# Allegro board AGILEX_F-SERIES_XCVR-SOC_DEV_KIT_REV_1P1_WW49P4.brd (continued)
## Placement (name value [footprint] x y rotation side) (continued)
R424  1K  [0402]  84.96 40.26 180 bottom
R425  1K  [0402]  83.57 40.26 180 bottom
R426  0  [0402]  94.21 33.53 270 bottom
R427  0  [0402]  94.21 34.54 270 bottom
R428  1K  [0402]  102.97 37.72 270 bottom
R429  0  [0402]  159.9 136.01 90 top
R430  0  [0402]  159.9 135 90 top
R431  0  [0402]  162.41 130.94 180 top
R432  0  [0402]  163.42 130.94 180 top
R433  1K  [0402]  170.15 142.05 0 top
R434  1K  [0402]  170.15 139.89 0 top
R435  DNI  [0402]  168.88 142.05 180 top
R436  1K  [0402]  161.01 130.81 0 top
R437  4.7K  [0402]  155.07 35.89 180 bottom
R438  10.0K  [0402]  154.81 101.85 90 top
R439  0  [0402]  159.99 34.29 90 bottom
R440  0  [0402]  159.99 33.02 90 bottom
R441  0  [0402]  161.29 94.36 270 top
R442  0  [0402]  159.99 29.21 90 bottom
R443  0  [0402]  159.99 27.94 90 bottom
R444  22  [0402]  155.57 27.51 180 bottom
R445  4.7K  [0402]  46.99 111.89 270 bottom
R446  10.0K  [0402]  52.58 168.78 270 top
R447  0  [0402]  46.1 162.31 90 top
R448  4.7K  [0402]  50.42 112.9 180 bottom
R449  0  [0402]  54.96 111.25 90 bottom
R450  0  [0402]  55.19 107.57 90 bottom
R451  0  [0402]  55.19 106.3 90 bottom
R452  0  [0402]  50.93 105.41 0 bottom
R453  4.7K  [0402]  186.28 49.4 0 top
R454  DNI  [0402]  187.42 47.37 0 top
R455  3.3K  [0402]  191.01 60.13 90 top
R456  DNI  [0402]  180.09 62.48 90 top
R457  DNI  [0402]  186.82 62.48 90 top
R458  0  [0402]  190.98 56.01 270 top
R459  0  [0402]  190.98 57.02 270 top
R460  100  [0402]  182.63 62.48 90 top
R461  0  [0402]  176.76 52.7 90 top
R462  0  [0402]  176.78 51.56 90 top
R463  22  [0402]  190.9 35.43 90 top
R464  124  [0402]  187.96 62.23 270 bottom
R465  0  [0402]  191.13 51.82 270 top
R466  0  [0402]  191.13 52.83 270 top
R467  DNI  [0402]  190.9 34.21 270 top
R468  374  [0402]  187.96 63.63 90 bottom
R469  124  [0402]  184.78 48.01 90 top
R470  DNI  [0402]  181.46 48.77 180 top
R471  DNI  [0402]  182.98 48.77 180 top
R472  374  [0402]  184.76 49.15 270 top
R475  0  [0402]  191.01 59.09 90 top
R476  1.00K  [0402]  179.8 42.29 0 top
R478  49.9  [0402]  172.06 58.8 90 top
R479  DNI  [0402]  164.44 47.12 270 top
R480  DNI  [0402]  145.77 91.44 270 bottom
R481  DNI  [0402]  145.77 92.71 270 bottom
R482  DNI  [0402]  143.48 92.71 90 bottom
R483  2.0K  [0402]  181.33 123.32 270 top
R484  10.0K  [0402]  181.74 128.52 180 top
R485  2.0K  [0402]  179.3 123.32 90 top
R486  10.0K  [0402]  180.47 128.52 180 top
R487  0  [0402]  143.48 91.44 90 bottom
R488  0  [0402]  143.48 95.25 90 bottom
R490  0  [0402]  180.09 95 270 top
R491  0  [0402]  180.09 93.73 270 top
R493  DNI  [0402]  180.09 92.46 270 top
R494  DNI  [0402]  180.09 96.27 270 top
R495  10.0K  [0402]  145.03 163.96 180 top
R496  10.0K  [0402]  146.18 152.4 90 bottom
R497  DNI  [0402]  172.72 121.28 180 top
R498  DNI  [0402]  171.32 121.28 180 top
R499  DNI  [0402]  183.64 125.73 0 top
R500  10.0K  [0402]  171.04 123.32 270 top
R501  10.0K  [0402]  173.07 123.32 90 top
R502  DNI  [0402]  61.47 44.7 270 bottom
R504  DNI  [0402]  175.51 125.73 0 top
R505  0  [0402]  61.47 45.97 90 bottom
R506  10.0K  [0402]  173.35 128.27 180 top
R507  10.0K  [0402]  172.34 128.27 180 top
R508  4.7K  [0402]  146.71 34.36 90 bottom
R509  40.2K  [0402]  36.34 193.42 270 bottom
R511  DNI  [0402]  36.42 186.44 0 top
R512  10.0K  [0402]  36.34 192.28 270 bottom
R513  10  [0402]  35.91 193.67 0 top
R514  0  [0402]  31.85 193.67 180 top
R515  20.0K  [0402]  30.71 193.67 0 top
R516  DNI  [0402]  35.15 186.44 0 top
R517  DNI  [0402]  52.32 212.85 0 bottom
R518  1.00K  [0402]  34.39 193.17 270 top
R519  DNI  [0402]  37.69 186.44 0 top
R520  3.3K  [0402]  7.97 186.56 90 bottom
R521  DNI  [0402]  31.72 186.69 90 bottom
R522  DNI  [0402]  11.53 182.4 0 top
R523  DNI  [0402]  13.33 140.49 0 top
R524  DNI  [0402]  33.37 187.2 180 bottom
R528  10.0K  [0402]  45.47 56.64 90 bottom
R529  422.00  [0402]  8.1 183.9 270 bottom
R530  10.0K  [0402]  45.47 55.75 270 bottom
R533  6.34M  [0402]  57.53 189.99 270 top
R534  10  [0402]  57.63 203.2 270 top
R535  1.00K  [0402]  50.26 191.26 90 top
R536  1K  [0402]  50.26 186.18 270 top
R537  DNI  [0402]  50.26 184.78 270 top
R538  DNI  [0402]  50.26 187.58 90 top
R539  45.3K  [0402]  55.88 189.36 180 top
R540  255K  [0402]  57.53 188.72 90 top
R541  3.3K  [0402]  190.98 214.18 180 bottom
R542  10.0K  [0402]  50.26 189.36 270 top
R543  1K  [0402]  181.91 196.06 0 top
R544  DNI  [0402]  180.67 196.06 0 top
R546  10.0K  [0402]  191.26 133.73 0 top
R547  DNI  [0402]  179.44 196.06 180 top
R548  10.0K  [0402]  189.99 133.73 180 top
R553  787  [0402]  205.36 185.17 0 top
R554  DNI  [0402]  34.11 148.74 270 bottom
R555  0  [0402]  32 148.74 90 bottom
R558  0  [0402]  43.99 25.53 180 top
R559  0  [0402]  42.85 25.53 180 top
R563  DNI  [0402]  207.49 184.89 180 bottom
R564  DNI  [0402]  201.78 184.73 180 bottom
R565  1K  [0402]  201.75 187.15 180 bottom
R566  DNI  [0402]  200.51 184.73 180 bottom
R569  0  [0402]  206.22 184.89 0 bottom
R573  422.00  [0402]  187.58 214.12 0 bottom
R574  DNI  [0402]  81.15 212.3 270 bottom
R575  DNI  [0402]  81.13 211.04 270 bottom
R576  DNI  [0402]  82.19 209.6 270 bottom
R636  10.0K  [0402]  37.28 162.1 180 bottom
R639  DNI  [0402]  30.33 146.81 180 bottom
R640  0  [0402]  31.34 146.81 180 bottom
R641  1K  [0402]  200.36 121.64 180 bottom
R643  0  [0402]  122.43 111.96 270 bottom
R644  0  [0402]  122.43 111.07 270 bottom
R646  DNI  [0402]  206.1 119.33 180 bottom
R647  DNI  [0402]  198.98 119.35 180 bottom
R648  DNI  [0402]  200.28 119.33 180 bottom
R654  0  [0402]  204.83 119.35 0 bottom
R658  10.0K  [0402]  36.17 160.02 180 top
R661  DNI  [0402]  32.48 146.81 180 bottom
R662  0  [0402]  33.5 146.81 0 bottom
R663  1K  [0402]  195.07 173.86 90 bottom
R666  0  [0402]  109.83 120.01 180 bottom
R667  0  [0402]  111.1 120.01 180 bottom
R668  6.34k  [0402]  215.39 167.39 180 bottom
R670  0  [0402]  184.35 168.12 270 bottom
R671  DNI  [0402]  187.32 165.48 90 bottom
R672  DNI  [0402]  187.32 168.28 90 bottom
R673  DNI  [0402]  187.32 166.88 90 bottom
R676  0  [0402]  189.1 165.1 180 bottom
R680  0  [0402]  24.31 43.48 0 bottom
R681  0.001  [WSL2010]  18.59 40.64 90 bottom
R682  DNI  [0402]  22.1 43.64 0 bottom
R684  19.6K  [0402]  26.9 42.6 180 bottom
R686  1K  [0402]  25.63 42.6 180 bottom
R687  Î  [0402]  29.39 41.91 180 top
R690  0.004  [0805]  130.53 26.83 180 bottom
R693  0  [0402]  140.11 21.74 0 bottom
R694  1K  [0402]  140.49 20.09 90 bottom
R695  DNI  [0402]  141.38 21.74 0 bottom
R697  10.0K  [0402]  50.52 167.89 270 bottom
R701  0  [0402]  7.72 44.88 90 bottom
R702  1K  [0402]  9.37 45.26 180 bottom
R703  0.001  [WSL2010]  2.67 45.26 90 bottom
R704  DNI  [0402]  7.72 46.15 90 bottom
R707  10.0K  [0402]  11.99 44.78 90 top
R718  0.004  [0805]  35.94 41.12 180 bottom
R719  DNI  [0402]  34.95 44.98 90 bottom
R722  0  [0402]  34.95 45.95 90 bottom
R724  1K  [0402]  36.83 44.09 180 bottom
R725  10.0K  [0402]  46.56 43.41 90 top
R728  0.04  [0805]  57.48 130.76 270 top
R731  DNI  [0402]  55.07 144.53 270 top
R732  0  [0402]  55.09 145.85 270 top
R734  1K  [0402]  57.38 145.92 270 top
R736  0.1  [0805]  50.37 50.88 180 top
R739  DNI  [0402]  66.93 53.11 90 top
R740  0  [0402]  66.93 51.84 90 top
R742  1K  [0402]  64.64 51.84 90 top
R744  DNI  [0402]  74.04 48.9 90 top
R745  10.0K  [0402]  74.04 47.62 90 top
R746  0  [0402]  74.04 50.16 270 top
R747  1K  [0402]  74.04 51.44 90 top
R750  0.001  [WSL2010]  112.99 28.22 0 bottom
R751  DNI  [0402]  116.64 21.74 0 bottom
R754  0  [0402]  115.37 21.74 0 bottom
R756  1K  [0402]  115.75 20.09 90 bottom
R757  10.0K  [0402]  46.94 167.59 0 bottom
R759  60.4k  [0402]  118.62 17.45 180 bottom
R760  37.4k  [0402]  118.75 19.53 90 bottom
R762  4.7K  [0402]  118.49 13.06 270 bottom
R763  4.7K  [0402]  119.38 23.85 90 bottom
R764  10.0K  [0402]  145.29 140.21 180 top
R765  DNI  [0402]  142.93 140.36 270 top
R766  0  [0402]  142.48 139.92 180 bottom
R767  1K  [0402]  140.84 140.34 90 top
R770  0  [0402]  161.93 25.43 0 bottom
R771  DNI  [0402]  163.19 25.43 0 bottom
R775  1K  [0402]  163.19 21.92 180 bottom
R776  10.0K  [0402]  47.14 164.51 0 bottom
R779  0  [0402]  95.22 21.74 0 bottom
R780  DNI  [0402]  96.49 21.74 0 bottom
R784  1K  [0402]  95.61 20.09 90 bottom
R785  10.0K  [0402]  50.52 168.91 270 bottom
R791  0  [0402]  46.18 18.97 90 top
R792  10.0K  [0402]  47.75 17.98 180 bottom
R794  60.4k  [0402]  40.46 16.43 0 bottom
R839  1.00K  [0402]  80.36 63.5 0 bottom
R841  1.00K  [0402]  65.99 80.82 90 bottom
R842  1.00K  [0402]  67.89 88.39 180 bottom
R843  1.00K  [0402]  35.31 17.65 0 top
R844  DNI  [0402]  30.1 135.13 180 bottom
R845  DNI  [0402]  102.97 36.45 90 bottom
R846  1K  [0402]  93.44 37.34 180 bottom
R847  1K  [0402]  168.88 139.89 180 top
R848  DNI  [0402]  167.49 130.94 0 top
R849  DNI  [0402]  46.99 110.87 270 bottom
R850  1K  [0402]  187.42 49.4 180 top
R851  1K  [0402]  182.37 125.73 0 top
R852  1K  [0402]  174.12 125.73 0 top
R855  0  [0402]  158.92 80.4 0 top
R856  0  [0402]  157.52 80.4 0 top
R857  4.70K  [0402]  154.28 151.76 180 bottom
R858  1.00K  [0402]  96.6 108.6 180 bottom
R859  1.00K  [0402]  96.27 106.78 300 bottom
R860  1.00K  [0402]  98.02 104.9 300 bottom
R861  1.00K  [0402]  97.89 105.79 300 bottom
R862  1.00K  [0402]  98.34 108.6 180 bottom
R863  1.00K  [0402]  98.77 106.85 60 bottom
R864  1.00K  [0402]  97.47 109.1 180 bottom
R865  1.00K  [0402]  97.51 107.11 0 bottom
R866  1.00K  [0402]  99.64 108.35 60 bottom
R867  1.00K  [0402]  99.64 107.35 60 bottom
R870  DNI  [0402]  155.29 206.76 270 bottom
R871  DNI  [0402]  155.29 205.49 270 bottom
R872  4.7K  [0402]  176.76 57.4 270 top
R873  4.7K  [0402]  191.01 58.04 270 bottom
R874  4.7K  [0402]  181.76 63.24 0 bottom
R875  4.7K  [0402]  180.24 63.24 0 bottom
R878  DNI  [0402]  164.47 50.67 270 top
R879  DNI  [0402]  164.47 51.69 270 top
R880  4.7K  [0402]  180.97 72.52 180 top
R881  4.7K  [0402]  181.99 72.52 180 top
R883  4.7K  [0402]  179.42 50.29 90 bottom
R884  4.7K  [0402]  179.42 51.56 90 bottom
R885  10.0K  [0402]  189.33 54.99 90 bottom
R886  10.0K  [0402]  189.33 56.13 90 bottom
R887  4.7K  [0402]  176.76 58.93 270 top
R888  4.7K  [0402]  176.76 60.07 270 top
R889  4.7K  [0402]  176.76 55.63 270 top
R890  4.7K  [0402]  176.76 54.61 270 top
R891  4.7K  [0402]  183.02 72.5 180 top
R892  4.7K  [0402]  184.02 72.52 180 top
R893  4.7K  [0402]  164.47 43.94 270 top
R894  4.7K  [0402]  164.47 44.96 270 top
R895  4.7K  [0402]  164.47 53.21 270 top
R896  4.7K  [0402]  164.47 54.23 270 top
R897  4.7K  [0402]  164.47 55.24 270 top
R898  4.7K  [0402]  164.47 56.26 270 top
R899  DNI  [0402]  80.26 34.16 90 top
R900  DNI  [0402]  80.26 35.18 90 top
R901  DNI  [0402]  161.9 34.29 270 top
R902  DNI  [0402]  161.9 33.02 270 top
R903  DNI  [0402]  161.9 29.21 270 top
R904  DNI  [0402]  161.9 27.94 270 top
R905  DNI  [0402]  57.28 110.06 270 top
R906  DNI  [0402]  57.28 111.33 270 top
R907  DNI  [0402]  193.11 56.01 90 bottom
R908  DNI  [0402]  193.14 57.02 90 bottom
R909  DNI  [0402]  174.34 61.47 270 top
R910  10.0K  [0402]  191.01 61.16 90 top
R911  DNI  [0402]  181.46 46.86 0 top
R912  DNI  [0402]  182.98 46.86 0 top
R913  4.7K  [0402]  164.47 48.64 270 top
R914  4.7K  [0402]  164.47 49.66 270 top
R915  22  [0402]  184.78 46.74 90 top
R916  DNI  [0402]  168.37 74.42 270 top
R917  100  [0402]  172.06 61.47 90 top
R918  DNI  [0402]  102.97 35.31 270 bottom
R919  DNI  [0402]  166.22 74.42 270 top
R920  DNI  [0402]  180.19 40.64 90 top
R921  DNI  [0402]  140.94 80.01 90 bottom
R922  0  [0402]  33.75 155.7 270 bottom
R923  10.0K  [0402]  166.72 128.52 180 top
R924  10.0K  [0402]  165.45 128.52 180 top
R925  0  [0402]  172.44 132.97 90 top
R926  0  [0402]  172.44 131.7 90 top
R927  0  [0402]  161.29 92.2 270 top
R928  10.0K  [0402]  29.33 165.86 0 bottom
R929  10.0K  [0402]  212.6 20.83 90 bottom
R930  10.0K  [0402]  212.6 19.56 90 bottom
R931  1.00K  [0402]  167.39 104.01 180 top
R932  0  [0402]  84.05 150.62 90 bottom
R933  0  [0402]  95.98 151 0 bottom
R934  0  [0402]  107.41 151 0 bottom
R935  0  [0402]  118.84 151.18 0 bottom
R936  0  [0402]  73.12 151 0 bottom
R937  240  [0402]  120.02 117.09 0 bottom
R938  240  [0402]  132.08 117.09 0 bottom
R939  422.00  [0402]  186.54 148.59 180 bottom
R940  0  [0402]  136.14 76.96 0 bottom
R941  0  [0402]  177.67 22.16 180 top
R942  0  [0402]  176.4 22.16 180 top
R943  DNI  [0402]  177.67 21.27 0 top
R944  DNI  [0402]  176.4 21.27 0 top
R945  10.0K  [0402]  187.81 153.86 0 bottom
R946  10.0K  [0402]  192.38 153.86 0 bottom
R947  0  [0402]  114.81 121.94 180 bottom
R948  DNI  [0402]  116.43 121.28 180 bottom
R949  120  [0402]  116.48 119.18 180 bottom
R950  DNI  [0402]  67.31 94.74 270 bottom
R951  DNI  [0402]  67.31 96.01 270 bottom
R952  DNI  [WSL2010]  66.34 116.48 270 top
R953  33  [0402]  143.48 88.9 90 bottom
R954  33  [0402]  143.48 90.17 90 bottom
R955  33  [0402]  143.48 93.98 90 bottom
R956  33  [0402]  140.94 91.44 90 bottom
R957  33  [0402]  140.94 86.36 90 bottom
R958  33  [0402]  140.94 87.63 90 bottom
R959  33  [0402]  140.94 92.71 90 bottom
R960  33  [0402]  140.94 95.25 90 bottom
R961  33  [0402]  140.94 81.28 270 bottom
R962  33  [0402]  140.94 90.17 270 bottom
R963  33  [0402]  140.94 88.9 270 bottom
R964  33  [0402]  140.94 93.98 270 bottom
R965  33  [0402]  140.94 85.09 270 bottom
R966  33  [0402]  140.94 83.82 270 bottom
R967  33  [0402]  140.94 82.55 270 bottom
R968  0  [0402]  165.45 130.94 180 top
R969  0  [0402]  166.47 130.94 180 top
R970  DNI  [0402]  157.74 137.08 270 top
R971  1K  [0402]  159.9 137.08 270 top
R972  1K  [0402]  163.8 142.05 180 top
R973  DNI  [0402]  163.8 139.89 180 top
R974  1K  [0402]  172.46 134.07 90 top
R975  DNI  [0402]  170.41 134.11 90 top
R976  0  [0402]  26.77 22.22 0 top
R977  0  [0402]  18.26 172.85 180 top
R980  1M  [1206]  9.42 25.48 0 bottom
R981  0  [0402]  171.85 98.96 270 bottom
R982  4.7K  [0402]  55.58 52.53 180 bottom
R984  10.0K  [0402]  43.51 56.64 90 bottom
R985  10.0K  [0402]  43.51 55.73 90 bottom
R986  499  [0402]  149.32 208.48 90 bottom
R987  10.0K  [0402]  154.28 203.45 90 bottom
R988  10.0K  [0402]  155.8 203.96 180 bottom
R989  10.0K  [0402]  154.28 204.47 270 bottom
R990  10.0K  [0402]  29.8 163.93 180 bottom
R991  10.0K  [0402]  28.93 161.8 0 top
R992  10.0K  [0402]  166.25 199.03 270 bottom
R993  10.0K  [0402]  166.25 200.65 270 bottom
R994  10.0K  [0402]  166.25 202.26 270 bottom
R995  10.0K  [0402]  166.25 203.88 270 bottom
R996  10.0K  [0402]  161.29 90.93 90 top
R997  0.001  [WIDE2512]  29.44 199.01 90 top
R998  0.001  [WIDE2512]  29.44 206.63 90 top
R999  4.7K  [0402]  164.47 45.97 270 top
R1000  DNI  [0402]  31.98 17.53 90 top
R1001  10.0K  [0402]  212.57 28.57 270 top
R1003  1K  [0402]  95.61 37.34 180 bottom
R1004  DNI  [0402]  156.25 80.4 180 top
R1005  DNI  [0402]  31.62 179.32 180 bottom
R1006  DNI  [0402]  87.2 153.31 90 bottom
R1007  DNI  [0402]  98.68 153.29 90 bottom
R1008  DNI  [0402]  110.06 153.31 90 bottom
R1009  DNI  [0402]  121.51 153.31 90 bottom
R1010  DNI  [0402]  75.77 153.31 90 bottom
R1013  DNI  [0402]  26.64 122.25 270 bottom
R1014  0  [0402]  26.64 123.52 270 bottom
R1018  1K  [0402]  24.99 123.14 0 bottom
R1019  10.0K  [0402]  21.98 123.7 270 bottom
R1024  0.004  [0805]  33.51 139.09 0 top
R1025  0  [0402]  135.38 80.01 0 bottom
R1026  0  [0402]  114.81 120.04 180 bottom
R1027  0  [0402]  114.78 114.43 180 bottom
R1028  0  [0402]  127.23 113.92 270 bottom
R1029  36  [0402]  129.13 145.54 90 top
R1030  36  [0402]  129.13 148.34 90 top
R1031  36  [0402]  129.13 153.67 270 bottom
R1032  36  [0402]  123.42 157.48 180 top
R1033  36  [0402]  129.13 153.67 90 top
R1034  36  [0402]  129.13 151.89 270 bottom
R1035  36  [0402]  129.13 152.78 90 top
R1036  36  [0402]  129.13 147.45 270 bottom
R1037  36  [0402]  126.08 157.48 180 top
R1038  36  [0402]  121.64 157.48 180 top
R1039  36  [0402]  125.19 157.48 180 top
R1040  36  [0402]  122.53 157.48 180 top
R1041  36  [0402]  129.13 149.22 270 bottom
R1042  36  [0402]  129.13 151 270 bottom
R1043  36  [0402]  129.13 149.22 90 top
R1044  36  [0402]  129.13 146.43 90 top
R1045  36  [0402]  129.13 147.45 90 top
R1046  36  [0402]  129.13 148.34 270 bottom
R1047  36  [0402]  129.13 152.78 270 bottom
R1048  36  [0402]  119.86 157.48 180 top
R1049  36  [0402]  124.31 157.48 180 top
R1050  36  [0402]  126.97 157.48 180 top
R1051  36  [0402]  120.75 157.48 180 top
R1052  36  [0402]  127.86 157.48 180 top
R1053  0  [0402]  191.06 58.06 90 top
R1054  DNI  [0402]  28.7 183.51 0 bottom
R1055  DNI  [0402]  30.1 183.51 0 bottom
R1056  DNI  [0402]  31.62 183.51 0 bottom
R1057  DNI  [0402]  33.02 183.51 0 bottom
R1058  1K  [0402]  28.7 181.48 0 bottom
R1059  1K  [0402]  30.1 181.48 180 bottom
R1060  1K  [0402]  31.62 181.48 0 bottom
R1061  1K  [0402]  33.02 181.48 0 bottom
R1062  3.3K  [0402]  169.1 43.92 90 top
R1063  3.3K  [0402]  169.11 44.75 90 top
R1064  DNI  [0402]  166.52 46.89 270 bottom
R1065  1.00K  [0402]  168.58 46.89 90 bottom
R1066  10.0K  [0402]  81.15 213.53 270 bottom
R1073  0  [0402]  75.99 198.99 270 top
R1074  DNI  [0402]  75.99 200.22 90 top
R1075  DNI  [0402]  78.91 215.32 180 top
R1098  1E  [0402]  85.42 201.35 90 top
R1100  0  [0402]  83.44 200.15 0 top
R1101  0  [0402]  89.03 199.64 270 top
R1105  0  [0402]  97.54 199.64 0 top
R1106  0  [0402]  103.12 199.14 270 top
R1110  0  [0402]  116.92 199.03 270 top
R1111  0  [0402]  111.33 199.54 0 top
R1119  DNI  [0402]  66.09 180.82 90 top
R1121  13.3K  [0402]  62.87 178.82 270 top
R1125  10.0K  [0402]  69.14 179.45 90 top
R1126  0  [0402]  66.04 179.45 90 top
R1129  10.0K  [0402]  171.7 176.53 90 top
R1130  DNI  [0402]  168.93 175.44 270 top
R1131  0  [0402]  171.7 179.07 270 top
R1134  4.22K  [0402]  181.48 167.13 90 top
R1138  DNI  [0402]  168.91 179.32 90 top
R1139  DNI  [0402]  168.9 178.08 90 top
R1140  1K  [0402]  171.73 172.52 90 top
R1141  0  [0402]  171.7 177.8 270 top
R1151  10.0K  [0402]  115.32 47.24 180 bottom
R1152  10.0K  [0402]  113.28 46.86 90 bottom
R1153  10.0K  [0402]  112.78 156.53 270 bottom
R1154  10.0K  [0402]  114.3 156.84 0 bottom
R2295  10.0K  [0402]  176.25 199.02 270 bottom
R2298  162K  [0402]  179.98 199.75 0 bottom
R5283  0  [0402]  141.22 163.96 0 top
R5284  0  [0402]  142.49 163.96 0 top
R5285  0  [0402]  143.76 163.96 0 top
R5286  DNI  [0402]  154.56 80.01 270 top
R5287  100  [0402]  22.5 56.97 180 bottom
R5288  100  [0402]  23.57 56.97 180 bottom
R5289  100  [0402]  26.77 56.97 180 bottom
R5290  100  [0402]  27.84 56.97 180 bottom
R5291  100  [0402]  33.53 56.62 90 bottom
R5292  100  [0402]  33.53 55.02 90 bottom
R5293  100  [0402]  33.53 53.95 90 bottom
R5294  100  [0402]  33.53 52.35 90 bottom
R5295  100  [0402]  33.53 51.28 90 bottom
R5296  100  [0402]  33.53 49.68 90 bottom
R5297  100  [0402]  33.53 48.59 90 bottom
R5298  100  [0402]  33.53 46.99 90 bottom
R5299  100  [0402]  28.12 45.64 0 bottom
R5300  100  [0402]  27 45.64 0 bottom
R5301  100  [0402]  24.43 45.59 0 bottom
R5302  100  [0402]  23.52 45.59 0 bottom
R5303  0  [0402]  43.99 44.27 90 bottom
R5304  0  [0402]  18.11 45.92 0 bottom
R5311  10.0K  [0402]  204.9 185.19 180 bottom
R5312  0.005  [0805]  200.81 206.38 270 top
R5316  10.0K  [0402]  204.7 187.22 270 bottom
R5317  10.0K  [0402]  203.05 187.25 180 bottom
R5318  10.0K  [0402]  208.58 186.94 180 bottom
R5319  4.99K  [0402]  195.68 199.92 270 bottom
R5320  10.7k  [0402]  207.39 186.94 0 bottom
R5322  11.3k  [0402]  208.08 185.17 180 top
R5323  0.005  [0805]  200.18 141.05 270 top
R5324  5.23k  [0402]  203.96 119.66 0 top
R5330  2.61k  [0402]  206.68 119.66 180 top
R5333  6.34k  [0402]  205.99 121.44 0 bottom
R5338  10.0K  [0402]  203.38 121.77 270 bottom
R5339  10.0K  [0402]  201.7 121.74 180 bottom
R5340  10.0K  [0402]  207.19 121.44 180 bottom
R5341  4.99K  [0402]  199.01 121.79 180 bottom
R5379  0  [0402]  75.72 54.23 270 top
R5380  0  [0402]  79.1 53.67 0 top
R5387  0  [0402]  138.68 141.86 270 top
R5388  0  [0402]  138.71 144.55 180 top
R5390  0  [0402]  35.36 36.68 180 bottom
R5391  49.9K  [0402]  35.13 34.34 90 bottom
R5392  49.9K  [0402]  35.13 33.02 270 bottom
R5393  0  [0402]  22.94 40.11 90 bottom
R5394  49.9K  [0402]  121.36 15.19 270 bottom
R5398  49.9K  [0402]  121.36 16.51 90 bottom
R5400  29.4K  [0402]  140.49 18.82 90 bottom
R5401  0  [0402]  140.92 16.1 180 bottom
R5402  0  [0402]  138 22.78 0 bottom
R5403  49.9K  [0402]  17.68 36.22 90 bottom
R5407  49.9K  [0402]  17.68 34.9 270 bottom
R5409  11.8K  [0402]  14.02 44.55 90 bottom
R5410  0  [0402]  18.14 32.59 0 bottom
R5411  0  [0402]  5.54 43.15 90 bottom
R5412  49.9K  [0402]  16.28 124.03 0 bottom
R5416  49.9K  [0402]  14.96 124.03 180 bottom
R5418  4.87k  [0402]  23.85 123.11 0 bottom
R5419  0  [0402]  19.61 123.72 270 bottom
R5420  0  [0402]  25.55 124.92 90 bottom
R5421  49.9K  [0402]  53.06 30.3 90 bottom
R5425  49.9K  [0402]  53.06 29.06 270 bottom
R5427  6.65K  [0402]  38.1 44.12 180 bottom
R5428  0  [0402]  48.87 25.5 270 bottom
R5429  0  [0402]  40.21 42.27 90 bottom
R5430  49.9K  [0402]  108.92 11.02 0 bottom
R5434  49.9K  [0402]  107.59 10.97 180 bottom
R5437  0  [0402]  115.8 13.84 180 bottom
R5438  0  [0402]  113.26 22.78 0 bottom
R5439  49.9K  [0402]  150.09 14.07 180 bottom
R5443  49.9K  [0402]  148.41 14.07 90 bottom
R5445  4.99K  [0402]  163.19 19.74 0 bottom
R5446  0  [0402]  163.53 15.67 90 bottom
R5447  0  [0402]  161.24 22.78 0 bottom
R5448  49.9K  [0402]  94.08 10.9 0 bottom
R5452  49.9K  [0402]  92.76 10.9 180 bottom
R5454  3.16K  [0402]  95.61 18.82 90 bottom
R5455  0  [0402]  96.04 14.4 0 bottom
R5456  0  [0402]  93.12 22.78 0 bottom
R5458  DNI  [0402]  168.88 176.78 90 top
R5459  10.0K  [0402]  166.47 178.74 270 bottom
R5460  10.0K  [0402]  166.5 180.14 270 bottom
R5461  10.0K  [0402]  179.4 167.13 270 top
R5463  10.0K  [0402]  171.72 173.78 270 top
R5466  0  [0402]  215.52 173.99 0 bottom
R5467  DNI  [0402]  195.07 180.59 270 bottom
R5468  DNI  [0402]  215.52 158.62 0 bottom
R5469  4.99k  [0402]  194.97 171.29 0 bottom
R5470  DNI  [0402]  196.47 165.41 180 bottom
R5472  DNI  [0402]  182.25 164.47 0 bottom
R5473  1K  [0402]  185.11 163.27 0 bottom
R5474  10.0K  [0402]  187.32 163.96 90 bottom
R5475  10.0K  [0402]  195.07 175.29 270 bottom
R5476  22.6K  [0402]  215.45 170.23 0 bottom
R5478  0  [0402]  195.07 176.66 270 bottom
R5479  1.62k  [0402]  195.07 177.93 90 bottom
R5480  0  [0402]  195.07 179.32 270 bottom
R5484  DNI  [0402]  48.92 18.03 90 top
R5690  825  [0402]  176.05 174.9 90 bottom
R5692  DNI  [0603]  175.21 171.27 180 bottom
R5875  10k  [0402]  81.16 212.32 90 top
R5876  10k  [0402]  83.38 212.31 90 top
R5881  499E  [0402]  74.12 203 0 top
R5882  499E  [0402]  77.85 202.95 180 top
R5883  499E  [0402]  76.59 203 0 top
R5893  0  [0402]  130.02 198.55 270 top
R5894  0  [0402]  124.43 199.06 0 top
R5963  DNI  [0603]  176.48 165.25 180 top
R5964  32.4K  [0603]  176.48 167.34 180 top
R5970  30.1k  [0402]  64.59 48.06 90 top
R5971  1E  [0402]  99.52 200.84 90 top
R5972  1E  [0402]  113.31 200.74 90 top
R5973  1E  [0402]  125.43 200.74 90 top
R5977  10.0K  [0402]  81.16 213.53 90 top
R5978  18.7K  [0402]  75.14 215.32 0 top
R5979  5.9K  [0402]  73.91 215.32 0 top
R5980  1.74K  [0402]  72.67 215.32 0 top
R5981  6.49K  [0402]  71.46 215.3 0 top
R5994  8.25K  [0402]  186.18 199.26 90 top
R5995  DNI  [0402]  176.25 197.78 270 bottom
R5996  0.002  [1206]  167.34 190.53 0 top
R5997  499E  [0402]  72.75 203 0 top
R5998  10.0K  [0402]  52.12 138.63 0 top
R5999  DNI  [0402]  51.82 141.6 90 top
R6005  DNI  [0402]  52.32 143.38 180 top
R6006  19.1k  [0402]  54.51 136.14 90 top
R6007  10.0K  [0402]  60.25 55.19 90 top
R6009  DNI  [0402]  53.67 53.16 0 top
R6013  DNI  [0402]  64.59 46.58 90 top
R6015  DNI  [0402]  44.3 19.43 180 top
R6016  DNI  [0402]  39.75 20.32 0 top
R6019  1K  [0402]  46.18 20.55 270 top
R6020  100K  [0402]  176.1 198.2 180 top
R6021  100K  [0402]  50.32 14.17 180 top
R6022  100K  [0402]  52.4 53.16 0 top
R6023  100K  [0402]  51.82 140.28 90 top
R6027  DNI  [0402]  60.51 177.82 0 top
R6028  100K  [0402]  72.54 177.67 270 top
R6034  162K  [0402]  72.62 180.32 90 top
R6035  10.0K  [0402]  74.24 213.58 270 bottom
R6036  6.49K  [0402]  71.4 212.8 0 top
R6037  DNI  [0603]  193.04 134.11 270 top
R6038  16.2k  [0603]  209.8 119.38 90 top
R6040  60.4k  [0402]  55.58 54.69 180 bottom
R6041  0  [0402]  71.03 208.81 0 top
R6042  0  [0402]  76.4 215.29 0 top
R6043  10.0K  [0402]  80.21 215.32 180 top
R6044  DNI  [0402]  32 41.2 0 bottom
R6045  DNI  [0402]  27.91 40.72 270 bottom
R6046  DNI  [0402]  139.98 13.56 270 bottom
R6049  DNI  [0402]  138.76 17.96 180 bottom
R6050  DNI  [0402]  15.82 43.36 180 bottom
R6053  DNI  [0402]  10.36 43.03 270 bottom
R6054  DNI  [0402]  30.68 129.16 270 bottom
R6057  DNI  [0402]  28.3 124.87 270 bottom
R6058  DNI  [0402]  48.31 45.19 0 bottom
R6061  DNI  [0402]  45.06 42.52 270 bottom
R6062  DNI  [0402]  121.03 18.14 270 bottom
R6065  DNI  [0402]  115.82 17.07 180 bottom
R6066  10.0K  [0402]  115.75 18.82 90 bottom
R6067  0  [0402]  163.55 13 270 bottom
R6070  0  [0402]  161.85 17.53 180 bottom
R6071  0  [0402]  95.73 23.85 270 bottom
R6074  0  [0402]  94.74 17.09 180 bottom
R6075  0  [0402]  30.3 40.56 270 bottom
R6076  0  [0402]  143.41 20.75 180 bottom
R6077  0  [0402]  13.21 43.03 270 bottom
R6078  0  [0402]  30.68 130.48 270 bottom
R6079  0  [0402]  49.73 45.03 0 bottom
R6080  0  [0402]  121.03 19.56 270 bottom
R6081  0  [0402]  163.53 14.33 270 bottom
R6082  0  [0402]  95.76 25.15 270 bottom
R6083  DNI  [0402]  88.09 18.44 270 bottom
R6084  DNI  [0402]  156.01 18.44 270 bottom
R6085  DNI  [0402]  108.61 18.41 270 bottom
R6086  DNI  [0402]  44.63 37.01 0 bottom
R6087  DNI  [0402]  23.8 125.2 180 bottom
R6088  DNI  [0402]  9.73 38.63 0 bottom
R6089  DNI  [0402]  132.87 18.41 270 bottom
R6090  DNI  [0402]  27.23 35 0 bottom
R6092  10k  [0402]  84.73 205.16 0 top
R6093  0  [0402]  84.46 203.05 0 top
R6094  0  [0402]  97.51 201.78 0 top
R6095  0  [0402]  111.29 201.63 0 top
R6096  0  [0402]  123.37 202.06 0 top
R6097  10k  [0402]  111.29 203.71 0 top
R6098  10k  [0402]  123.27 204.17 0 top
R6099  10k  [0402]  97.48 203.91 0 top
S1  PB Switch  [WURTH_6X3P5_TACT_SWITCH]  137.54 198.37 270 top
S2  PB Switch  [WURTH_6X3P5_TACT_SWITCH]  141.99 198.37 270 top
S3  PB Switch  [WURTH_6X3P5_TACT_SWITCH]  146.43 198.37 270 top
S4  PB Switch  [WURTH_6X3P5_TACT_SWITCH]  150.88 198.37 270 top
S5  PB Switch  [WURTH_6X3P5_TACT_SWITCH]  155.32 198.37 270 top
S6  PB Switch  [WURTH_6X3P5_TACT_SWITCH]  159.77 198.37 270 top
S7  PB Switch  [WURTH_6X3P5_TACT_SWITCH]  164.21 198.37 270 top
S8  PB Switch  [WURTH_6X3P5_TACT_SWITCH]  168.66 198.37 270 top
S10  PB Switch  [WURTH_6X3P5_TACT_SWITCH]  180.57 173.81 90 top
S13  PB Switch  [WURTH_6X3P5_TACT_SWITCH]  169.54 157.23 270 top
S14  PB Switch  [WURTH_6X3P5_TACT_SWITCH]  174.12 157.23 270 top
S15  PB Switch  [WURTH_6X3P5_TACT_SWITCH]  183.26 157.23 270 top
S16  PB Switch  [WURTH_6X3P5_TACT_SWITCH]  178.69 157.23 270 top
S17  PB Switch  [WURTH_6X3P5_TACT_SWITCH]  187.83 157.23 270 top
S18  PB Switch  [WURTH_6X3P5_TACT_SWITCH]  192.41 157.23 270 top
ST1  -  [SHORT]  204.72 192.41 0 bottom
ST2  -  [SHORT]  204.62 127.64 0 bottom
ST3  -  [SHORT]  205.05 167.59 0 bottom
ST4  -  [SHORT]  32.28 34.42 0 bottom
ST5  -  [SHORT]  133.17 13.13 270 bottom
ST6  -  [SHORT]  15.21 37.67 0 bottom
ST8  -  [SHORT]  49.68 37.21 0 bottom
ST9  -  [SHORT]  108.58 13.26 270 bottom
ST10  -  [SHORT]  156.79 13.26 270 bottom
ST11  -  [SHORT]  88.52 13.03 270 bottom
ST13  -  [SHORT]  55.8 140.97 270 bottom
ST16  -  [SHORT]  16.71 145.08 0 bottom
ST18  -  [SHORT]  178.82 199.9 180 bottom
ST19  -  [SHORT]  157.63 179.32 0 bottom
ST20  -  [SHORT]  58.06 49.2 180 bottom
ST21  -  [SHORT]  43.31 16.64 180 bottom
SW1  TDA04H0SB1  [DIPSWITCH_SMT_QUAD]  151.13 157.35 0 top
SW2  TDA08H0SB1  [DIPSWITCH_SMT_OCTAL]  188.78 173.84 0 top
SW3  TDA08H0SB1  [DIPSWITCH_SMT_OCTAL]  188.78 186.41 0 top
SW4  TDA04H0SB1  [DIPSWITCH_SMT_QUAD]  179.37 186.76 0 top
SW5  TDA04H0SB1  [DIPSWITCH_SMT_QUAD]  158.98 157.35 0 top
SW6  TDA04H0SB1  [DIPSWITCH_SMT_QUAD]  143.13 157.35 0 top
SW8  EG2201A  [SWSPDT]  18.9 132.84 180 top
SW9  TDA02H0SB1  [DIPSWITCH_SMT_2POS]  175.99 173.68 90 top
SW10  TDA02H0SB1  [DIPSWITCH_SMT_2POS]  164.82 157.35 90 top
TP1  VIA_1  [TP_020RD_SMT]  161.54 125.35 0 top
TP2  VIA_1  [TP_020RD_SMT]  160.4 125.35 0 top
TP3  VIA_1  [TP_020RD_SMT]  159.33 125.35 0 top
TP21  VIA_1  [TP_020RD_SMT]  169.52 131.98 0 top
TP22  VIA_1  [TP_020RD_SMT]  169.57 133.07 0 top
TP32  VIA_1  [TP_020RD_SMT]  168.28 161.29 180 bottom
TP33  VIA_1  [TP_020RD_SMT]  163.07 152.15 180 bottom
TP39  VIA_1  [TP_020RD_SMT]  31.29 41.76 90 top
TP40  VIA_1  [TP_020RD_SMT]  24.36 41.38 90 top
TP41  VIA_1  [TP_020RD_SMT]  140.92 14.61 0 top
TP42  VIA_1  [TP_020RD_SMT]  140.77 19.71 0 top
TP43  VIA_1  [TP_020RD_SMT]  13.46 44.41 90 top
TP44  VIA_1  [TP_020RD_SMT]  9.3 44.98 90 top
TP45  VIA_1  [TP_020RD_SMT]  31.27 135.61 0 top
TP46  VIA_1  [TP_020RD_SMT]  25.98 130.25 0 top
TP47  VIA_1  [TP_020RD_SMT]  49 43.74 90 top
TP48  VIA_1  [TP_020RD_SMT]  41.17 43.46 90 top
TP49  VIA_1  [TP_020RD_SMT]  115.39 15.46 0 top
TP50  VIA_1  [TP_020RD_SMT]  116.2 20.98 0 top
TP51  VIA_1  [TP_020RD_SMT]  163.88 13.06 0 top
TP52  VIA_1  [TP_020RD_SMT]  164.41 20.14 0 top
TP53  VIA_1  [TP_020RD_SMT]  94.46 12.85 0 top
TP54  VIA_1  [TP_020RD_SMT]  94.39 18.59 0 top
TP56  VIA_1  [TP_020RD_SMT]  136.48 182.1 0 top
TP60  VIA_1  [TP_020RD_SMT]  190.25 165.99 0 top
TP62  VIA_1  [TP_020RD_SMT]  190.25 163.45 0 top
TP63  VIA_1  [TP_020RD_SMT]  190.25 168.15 0 top
TP64  VIA_1  [TP_020RD_SMT]  199.77 181.48 0 top
TP65  VIA_1  [TP_020RD_SMT]  140.92 17.07 0 top
TP72  VIA_1  [TP_020RD_SMT]  72.75 183.21 0 top
TP73  VIA_1  [TP_020RD_SMT]  75.11 183.24 0 top
TP79  VIA_1  [TP_020RD_SMT]  186.31 165.86 0 top
TP80  VIA_1  [TP_020RD_SMT]  206.63 181.23 0 top
TP91  VIA_1  [TP_020RD_SMT]  194.89 204.77 0 top
TP92  VIA_1  [TP_020RD_SMT]  214.38 206.25 0 top
TP97  VIA_1  [TP_020RD_SMT]  192.79 137.16 0 top
TP98  VIA_1  [TP_020RD_SMT]  215.65 137.29 0 top
TP107  VIA_1  [TP_020RD_SMT]  139.24 186.11 0 top
TP108  VIA_1  [TP_020RD_SMT]  170.92 193.34 0 top
TP109  VIA_1  [TP_020RD_SMT]  27.3 41.53 0 top
TP122  VIA_1  [TP_020RD_SMT]  13.69 47.29 0 top
TP123  VIA_1  [TP_020RD_SMT]  25.88 136.32 0 top
TP132  VIA_1  [TP_020RD_SMT]  44.32 43.48 0 top
TP133  VIA_1  [TP_020RD_SMT]  46.74 140.21 0 top
TP134  VIA_1  [TP_020RD_SMT]  46.74 138.18 0 top
TP138  VIA_1  [TP_020RD_SMT]  61.52 42.6 0 top
TP139  VIA_1  [TP_020RD_SMT]  63.55 42.57 0 top
TP154  VIA_1  [TP_020RD_SMT]  115.44 18.29 0 top
TP163  VIA_1  [TP_020RD_SMT]  164.39 16.76 0 top
TP164  VIA_1  [TP_020RD_SMT]  94.46 15.82 0 top
TP165  VIA_1  [TP_020RD_SMT]  58.34 170.43 0 top
TP166  VIA_1  [TP_020RD_SMT]  174.17 208.66 0 top
TP167  VIA_1  [TP_020RD_SMT]  184.56 209.22 0 top
TP169  VIA_1  [TP_020RD_SMT]  196.37 184.71 0 top
TP171  VIA_1  [TP_020RD_SMT]  170.59 169.11 0 top
TP172  VIA_1  [TP_020RD_SMT]  199.57 119.15 0 top
TP173  VIA_1  [TP_020RD_SMT]  214.68 150.27 0 top
TP174  VIA_1  [TP_020RD_SMT]  20.93 43.99 0 top
TP175  VIA_1  [TP_020RD_SMT]  140.61 26.01 0 top
TP176  VIA_1  [TP_020RD_SMT]  11.2 50.52 0 top
TP177  VIA_1  [TP_020RD_SMT]  36.09 140.84 0 top
TP178  VIA_1  [TP_020RD_SMT]  32.79 43.28 0 top
TP179  VIA_1  [TP_020RD_SMT]  53.14 130.96 0 top
TP180  VIA_1  [TP_020RD_SMT]  50.32 54.66 0 top
TP181  VIA_1  [TP_020RD_SMT]  116.13 25.04 0 top
TP182  VIA_1  [TP_020RD_SMT]  84.58 53.47 0 top
TP183  VIA_1  [TP_020RD_SMT]  138.23 151.87 0 top
TP184  VIA_1  [TP_020RD_SMT]  144.02 24.99 0 top
TP185  VIA_1  [TP_020RD_SMT]  79.22 28.6 0 top
TP186  VIA_1  [TP_020RD_SMT]  35.33 13.89 0 top
TP187  VIA_1  [TP_020RD_SMT]  47.62 23.24 0 top
TP188  VIA_1  [TP_020RD_SMT]  49.66 23.22 0 top
TP189  VIA_1  [TP_020RD_SMT]  173.71 198.88 0 top
TP190  VIA_1  [TP_020RD_SMT]  176.58 196.01 0 top
TP191  VIA_1  [TP_020RD_SMT]  209.98 184.25 0 top
TP192  VIA_1  [TP_020RD_SMT]  205.36 113.13 0 top
TP193  VIA_1  [TP_020RD_SMT]  194.46 165.13 0 top
U1  AGFB014R24A  [F2486A]  111.76 101.6 0 top
U2  MAX3378_UCSP  [UCSP-12]  78.99 60.71 0 top
U3  MT40A1G16RC-062E:B  [FBGA96]  88.14 147.32 180 top
U4  MT40A1G16RC-062E:B  [FBGA96]  99.57 147.32 180 top
U5  MT40A1G16RC-062E:B  [FBGA96]  111 147.32 180 top
U6  MT40A1G16RC-062E:B  [FBGA96]  122.43 147.32 180 top
U7  MT40A1G16RC-062E:B  [FBGA96]  76.71 147.32 180 top
U10  MAX3378_UCSP  [UCSP-12]  66.04 83.95 270 top
U11  MAX3378_UCSP  [UCSP-12]  55.5 83.95 270 top
U12  202718-0100  [202718]  48.12 69.34 270 top
U13  MAX3378_UCSP  [UCSP-12]  66.04 90.42 270 top
U14  MAX3378_UCSP  [UCSP-12]  55.5 90.42 270 top
U15  88E1111  [BCC96]  24.89 15.24 270 top
U16  MAX3378_UCSP  [UCSP-12]  34.67 20.32 270 top
U17  MAX3378_UCSP  [UCSP-12]  155.96 147.57 180 top
U18  SN74AVC4T234ZWAR  [ZSU]  167.51 208.41 0 top
U19  SN74AVC4T234ZWAR  [ZSU]  160.78 208.53 0 top
U20  DRTR5V0U2SR-7  [HC_TK0_SOT143_4_1400X2885_1920_MA]  17.14 175.9 90 bottom
U21  CY7C68013A_QFN  [QFN56]  24.05 176.53 0 top
U22  MAX811  [SOT-143]  30.96 153.54 0 bottom
U23  10M16SCU324C8G  [UBGA324]  38.73 172.72 90 top
U24  IDTQS3861  [QSOP24P]  32.77 140.21 0 bottom
U25  IDTQS3861  [QSOP24P]  42.93 140.21 0 bottom
U28  MAX811  [SOT-143]  26.93 167.64 180 top
U29  10M16SCU324C8G  [UBGA324]  171.07 93.98 90 top
U31  MAX6581  [24TQFN-EP]  170.94 111.89 270 top
U32  LTC2497CUHF#PBF  [LTQFN38]  43.81 51.82 270 bottom
U33  LTC2497CUHF#PBF  [LTQFN38]  23.88 51.82 270 bottom
U34  Si53311  [QFN_32]  86.98 35 270 bottom
U35  Si52204-A01BGM  [QFN32L]  165.1 135.51 270 top
U36  Si5338K-B10518-GM  [QFN24]  155.83 31.32 0 bottom
U37  Si5338K-B10419-GM  [QFN24]  51.18 109.35 0 bottom
U38  LMK05028  [QFN64_TI]  183.51 56.13 270 top
U39  48MHz  [OSC2520]  183.39 43.69 0 top
U40  MAX3378_UCSP  [UCSP-12]  167 50.16 90 top
U41  MAX3378_UCSP  [UCSP-12]  182.75 69.72 0 top
U42  MAX3378_UCSP  [UCSP-12]  167 54.74 90 top
U43  FXMA2102UMX  [UMLP]  180.47 126.24 0 top
U44  24LC32A  [SO8]  67.06 45.34 180 bottom
U45  FXMA2102UMX  [UMLP]  172.21 126.24 0 top
U46  DS1339C  [SO16_WIDE]  139.09 31.19 270 bottom
U47  FDMC8010  [POWER33]  35.66 202.56 180 top
U48  LTC4218CDHC-12#PBF  [16-LEAD_PLASTIC_DFN]  32.61 190.12 0 top
U49  LTM4623EY#PBF  [HC_TK0_BGA25_S6325_1_1270_MA]  67.91 175.06 0 top
U50  FDMC8010  [POWER33]  53.85 202.56 180 top
U51  LTC4365CDDB-1#TRMPBF  [DFN8-EPAD_3X2]  53.31 189.36 90 top
U52  LTM4623EY#PBF  [HC_TK0_BGA25_S6325_1_1270_MA]  180.67 201.47 180 top
U53  LTM4678EY#PBF  [HC_BGA144C127P12X12_1600X1600X626]  204.72 195.71 270 top
U54  LTC3888IUHG-1#PBF  [HC_TK1_LCC52_5100X8100_DF3650X6650_MA_MFG]  74.81 208.96 180 top
U57  LTM4680EY#PBF  [BGA144_REVC_ADI]  156.36 181.89 270 top
U58  LTM4678EY#PBF  [HC_BGA144C127P12X12_1600X1600X626]  203.33 130.2 270 top
U59  LTM4677EY#PBF  [HC_TK0_BGA144_S16075_1_1270_MA]  206.32 166.12 180 top
U60  LTM4608AEV#PBF  [BGA68_15X9_ADI]  27.05 35.18 270 top
U61  LTM4608AEV#PBF  [BGA68_15X9_ADI]  133.07 18.67 180 top
U62  LTM4608AEV#PBF  [BGA68_15X9_ADI]  9.65 38.23 270 top
U63  LTM4608AEV#PBF  [BGA68_15X9_ADI]  22.12 143.71 90 top
U64  LTM4608AEV#PBF  [BGA68_15X9_ADI]  44.32 37.34 270 top
U65  LTM4623EY#PBF  [HC_TK0_BGA25_S6325_1_1270_MA]  56.52 140.34 90 top
U66  LTM4623EY#PBF  [HC_TK0_BGA25_S6325_1_1270_MA]  59.89 50.11 270 top
U67  NCP51200MNTXG  [DFN10_3X3_ONS]  77.65 50.88 180 top
U68  LTM4608AEV#PBF  [BGA68_15X9_ADI]  108.33 18.67 180 top
U69  NCP51200MNTXG  [DFN10_3X3_ONS]  141.48 143.51 270 top
U70  LTM4608AEV#PBF  [BGA68_15X9_ADI]  156.31 18.67 180 top
U71  LTM4608AEV#PBF  [BGA68_15X9_ADI]  88.19 18.67 180 top
U72  LTM4623EY#PBF  [HC_TK0_BGA25_S6325_1_1270_MA]  44.07 14.83 0 top
U79  MAX3378_UCSP  [UCSP-12]  167 44.96 90 top
U80  10MHz  [SMD7X5]  170.03 67.79 270 top
U81  FXMA2102UMX  [UMLP]  165.86 126.24 0 top
U82  LM339PW  [PW]  160.75 201.55 90 bottom
U83  NTTFS4C05NTAG  [FDMC8878_VER2]  198.09 12.45 0 top
U84  LTC4357IDCB#TRMPBF  [DFN6_EPAD]  205.59 6.86 270 top
U87  LTC7051AV#PBF  [LQFN42_5X8X0P95_ADI]  86.87 195.96 90 top
U88  LTC7051AV#PBF  [LQFN42_5X8X0P95_ADI]  100.97 195.45 90 top
U89  LTC7051AV#PBF  [LQFN42_5X8X0P95_ADI]  114.76 195.35 90 top
U90  LTC7051AV#PBF  [LQFN42_5X8X0P95_ADI]  127.86 194.87 90 top
V2  SENSE_PAD  [SENSE]  28.93 193.67 0 top
V3  SENSE_PAD  [SENSE]  29.69 193.67 0 top
V4  SENSE_PAD  [SENSE]  68.58 177.22 180 bottom
V8  SENSE_PAD  [SENSE]  20.88 40.23 270 bottom
V9  SENSE_PAD  [SENSE]  20.85 41.1 270 bottom
V10  SENSE_PAD  [SENSE]  128.6 26.45 90 bottom
V11  SENSE_PAD  [SENSE]  128.6 27.19 90 bottom
V12  SENSE_PAD  [SENSE]  4.95 44.86 270 bottom
V13  SENSE_PAD  [SENSE]  4.93 45.72 270 bottom
V16  SENSE_PAD  [SENSE]  33.93 40.69 90 bottom
V17  SENSE_PAD  [SENSE]  33.91 41.55 90 bottom
V18  SENSE_PAD  [SENSE]  54.46 129.03 270 top
V19  SENSE_PAD  [SENSE]  54.46 129.64 270 top
V20  SENSE_PAD  [SENSE]  48.92 48.85 0 top
V21  SENSE_PAD  [SENSE]  48.21 48.85 0 top
V22  SENSE_PAD  [SENSE]  112.53 30.48 0 bottom
V23  SENSE_PAD  [SENSE]  113.4 30.51 0 bottom
V24  SENSE_PAD  [SENSE]  35.15 138.71 90 top
V25  SENSE_PAD  [SENSE]  35.15 139.37 90 top
X1  25.00MHz  [XTAL_SG310]  21.72 7.24 0 top
X2  50MHz  [OSC_4PIN_SMD_5X7]  156.46 96.9 270 top
X3  50MHz  [OSC_4PIN_SMD_5X7]  51.82 164.47 180 top
Y1  24.00MHz  [XTAL_FA-128]  16.83 181.52 0 top
Y2  549BACB000118BBG  [OSC_SMD_8PIN_3_2X5]  99.44 34.04 270 bottom
Y3  25.00MHz  [XTAL_FA-128]  165.96 142.46 0 top
Y4  25.00MHz  [XTAL_FA-128]  149.71 30.23 270 bottom
Y5  25.00MHz  [XTAL_FA-128]  45.06 108.33 0 bottom

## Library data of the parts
B1 = Molex_zQSFP_Cage
BT1 = BATTERY
C1 C8 C17-C38 C41-C50 C163 C205 C206 C245 C246 C373 C377 C387 C489 C497 C519 C547 C550 C574 C577 C581 C586-C607 C615-C623 C626 C632-C636 C651 C654 C657 C659 C662 C665 C666 C680 C683 C686 C791-C793 C795 C796 C802 C806 C819 C821-C830 C837 C843 C847 C854-C856 C883 C884 C887 C890 C893 C896 C898 C901 C904 C907 C910 C912 C916 C920 C922 C925 C928 C931 C934 C937 C940 C948 C949 C955-C958 C970 C987 C988 C1104 C1105 C1122 C1125 C1137 C1146 C1155 C1170 C1200 C1218 C1227 C1325-C1327 C1329 C1333 C1334 C1408 C1427-C1440 C1457 C1458 C1463 C1466 C1468-C1483 C1489-C1496 C1499-C1514 C1520-C1527 C1530-C1537 C1551-C1554 C1561-C1580 C1589-C1592 C1600 C1609-C1611 C1613 C1622 C1628 C1636 C1637 C1720 C1721 C1777 C1779 C1780 C1782 C1784 C1786 C1814 C1827 C1843 C1848 C1858-C1874 C1895 C1899 C1900 C1921-C1923 C1931 C1934 C1937 C1939 C1941 C1943 C1945-C1951 C1953 C1954 C1956 C1957 C1959 C1961 C1966 C1967 C1970 C1975 C1976 C2000-C2002 C2047 C2062 C2063 C2076 C2079 C2086 C2091 C2094 C2097-C2100 C2108 C2110 C2113-C2118 C2131-C2138 = CAP: Tolerance: TOL; User Part Number: PART#
C2 C3 C5 C7 C11 C140 C312-C318 C372 C374 C406 C407 C452 C453 C498 C521 C522 C525 C526 C528-C531 C533 C534 C536 C537 C544 C546 C548 C549 C551 C553 C554 C556 C559 C561 C565 C569 C573 C575 C576 C578 C580 C582 C583 C585 C610-C614 C625 C627-C631 C637-C650 C652 C653 C655 C656 C658 C660 C661 C663 C664 C668-C679 C681 C682 C684 C685 C688-C697 C699-C708 C710-C718 C720-C726 C728-C731 C733 C734 C736-C738 C741-C748 C750-C753 C755-C761 C763-C766 C768-C775 C777-C781 C783-C790 C794 C798 C800 C803 C807 C809-C818 C820 C831-C836 C838-C842 C844-C846 C848-C853 C857 C858 C861 C866 C882 C885 C886 C888 C889 C891 C892 C894 C895 C897 C899 C900 C902 C903 C905 C906 C908 C909 C911 C913-C915 C917-C919 C921 C923 C924 C926 C927 C929 C930 C932 C933 C935 C936 C938 C939 C941-C947 C965 C1328 C1330-C1332 C1335 C1336 C1390-C1405 C1409-C1411 C1413 C1414 C1416 C1417 C1588 C1595 C1597 = CAP: Tolerance: TOL; User Part Number: PART#; signal model: CAP_0402_0.1UF_0.1uF
C4 C6 C13 C16 C76 C77 C147-C150 C164 C165 C181 C194-C196 C199 C202-C204 C247-C250 C252 C273 C274 C293 C294 C337 C338 C348 C349 C399 C486 C487 C491 C492 C520 C523 C524 C527 C532 C535 C545 C552 C555 C557 C558 C560 C562-C564 C566-C568 C570-C572 C579 C584 C624 C667 C687 C698 C709 C719 C727 C732 C735 C740 C749 C754 C762 C767 C776 C782 C797 C799 C804 C808 C976-C983 C989-C995 C1094-C1101 C1107-C1113 C1116-C1121 C1123 C1124 C1130-C1133 C1136 C1138 C1145 C1148 C1154 C1156 C1169 C1171 C1178 C1179 C1181 C1182 C1184-C1187 C1199 C1201 C1217 C1219 C1226 C1228 C1237 C1238 C1290-C1310 C1319 C1378-C1380 C1389 C1412 C1415 C1484-C1488 C1497 C1498 C1515-C1519 C1528 C1529 C1546 C1547 C1559 C1560 C1581-C1587 C1612 C1614 C1623-C1626 C1650 C1719 C1774-C1776 C1781 C1783 C1788-C1795 C1798 C1799 C1803-C1805 C1809-C1813 C1815 C1817 C1840 C1842 C1845-C1847 C1979 C1998 C2017 C2044 C2045 C2048 C2064-C2067 C2095 C2096 = CAP: Tolerance: *; User Part Number: *
C9 C10 C258-C260 C859 C860 C862 C863 C865 C868-C876 = CAP: signal model: CAP_0201_0.1UF_0.1uF
C12 C80-C85 C87-C109 C141-C146 C192 C193 C207 C208 C211 C212 C253 C261 C339 C350-C352 C395 C1424-C1426 C1441-C1448 C1461 C1627 C1879-C1881 = CAP: User Part Number: PART#; Tolerance: TOL
C14 C15 C39 C40 C71 C73-C75 C78 C79 C120-C122 C124-C127 C130 C132-C136 C139 C151-C162 C166-C173 C175-C180 C182-C191 C197 C198 C201 C213-C218 C222-C235 C254-C257 C262 C263 C268-C272 C275-C292 C344-C347 C371 C1337-C1377 C1381-C1388 = CAP
C209 C210 C950 C951 C984 C985 C1102 C1103 C1129 C1140 C1141 C1149 C1150 C1157 C1158 C1172 C1173 C1202 C1203 C1220 C1221 C1229 C1230 C1615 C1616 C1743 C1796 C1896 C1901 = PCAP: User Part Number: PART#; Tolerance: TOL
C328 C952-C954 C966-C969 C1593 C1594 C1598 C1599 = PCAP: Tolerance: TOL; User Part Number: PART#
C375 C400 = Cap 0.1UF 25VDC 0402: Tolerance: TOL; User Part Number: PART#
C608 C609 C1596 = Cap, NP, 1206: Tolerance: *; User Part Number: *
C801 C805 = Cap 100PF 5% 50VDC 0402: Tolerance: TOL; User Part Number: PART#
C986 = Cap, NP, 0402: Tolerance: *; User Part Number: *
C1316-C1318 C1801 C1802 C1807 C1808 = PCAP
C1629 C1664 C1687 C1709 C1733 C1844 C2068-C2070 C2119 C2122 C2125 C2128 = CAPPOL
C1652 C1669 C1670 C1688 C1689 C1711 C1712 C1718 C1734 C1735 C1978 C1997 C2016 = Cap, NP, 0402: Tolerance: TOL; User Part Number: PART#
C1660 C1661 C1682 C1683 C1703 C1704 C1726 C1727 C2120 C2121 C2123 C2124 C2126 C2127 C2129 C2130 = Cap, NP, 0805: User Part Number: PART#; Tolerance: TOL
C1665-C1668 C1690-C1693 C1713-C1716 C1736-C1739 = Cap, NP, 1206: User Part Number: PART#; Tolerance: TOL
C1960 C2101 = CAP0603_1: Tolerance: *; User Part Number: *
C1962 = CAP0603_1: Tolerance: TOL; User Part Number: PART#
CN1 = CN-USB
CON1 = DDR4_72b-ECC_SODIMM_260Pin
D1 D41 = LT1389
D2-D10 D15-D20 D27-D30 D36-D40 = LED_WE1206
D11-D14 D23 D24 D33 D34 = LED_0
D35 = ZENERDIODE
FB1 FB4-FB10 FB14 FB15 = INDUCTOR: Tolerance: TOL; User Part Number: PART#
J1-J4 J6 J7 J22-J25 J28 J30 J50 = SMA_0
J5 = QSH-030-01-C-D-A
J10 J11 = HEADER 30X2_0
J12 = Molex_zQSFP_Conn
J13 = 2x8 MXP
J14 = PCIE_Bracket_X16_0
J15 = HFJ11-1G02E: Tolerance: *; User Part Number: *
J16-J18 J35 J49 = 2x5: User Part Number: *; Tolerance: *
J19 = 70247-1051
J20 J21 = FAN_Conn_0
J26 = HDR2X10: Tolerance: *; User Part Number: *
J27 J29 J31 J34 = CONN, SMA
J37 = PCIe 2x3 ATX_1
J51 = 1x3_HDR_TH
L1 L47-L49 = Inductor, Discrete
L2 L6 L20-L35 L40 L42 = IND Ferrite 0603 3A/30 Ohms: User Part Number: *; Tolerance: *
L5 = IND Ferrite 0603 3A/30 Ohms: Tolerance: *; User Part Number: *
L8 L9 L18 L19 = BEAD_FERRITE_SM: Tolerance: TOL; User Part Number: PART#
L10-L12 L39 L41 = Inductor_smd_1
L13-L15 = Inductor_smd_1: User Part Number: IND_WURTH_74479276210; Tolerance: ?
L16 L17 = IND Ferrite 0402 300mA/220: Tolerance: TOL; User Part Number: PART#
L51 = BEAD_FERRITE_SM: Tolerance: *; User Part Number: *
MTH3-MTH5 = MNT HOLE_1
Q1-Q3 = 2N2222_2: Tolerance: *; User Part Number: *
Q4 Q5 Q7 = PWRMOSFET_EN_GSD_0
Q6 = MMBT3906/SOT_3: Tolerance: *; User Part Number: *
R1 R2 R7 R23-R26 R37 R38 R49-R52 R54 R59 R64 R74-R77 R82-R84 R88 R104 R108-R112 R139 R141 R144 R189 R191-R193 R200 R204-R206 R208 R223 R228 R234 R251 R351 R354-R357 R396 R397 R409 R454 R456 R457 R460 R463 R479 R499 R502 R504 R516 R517 R536 R538 R543 R547 R554 R563-R566 R639 R641 R646-R648 R661 R663 R671-R673 R682 R686 R694 R695 R719 R724 R731 R734 R739 R742 R744 R751 R756 R765 R771 R775 R780 R784 R844 R870 R871 R878 R879 R899-R912 R916 R918-R921 R932-R938 R943 R944 R1000 R1004 R1005 R1013 R1018 R1053 = RESISTOR: Tolerance: TOL; User Part Number: PART#; signal model: RESISTOR_0402_DNI_DNI
R3-R6 R8-R13 R15 R18-R22 R27-R32 R34 R36 R39-R42 R45-R48 R53 R55-R58 R60-R63 R65-R73 R79-R81 R87 R89 R102 R103 R105-R107 R116-R138 R140 R142 R143 R145 R146 R180-R183 R194-R199 R201-R203 R207 R209-R222 R224-R227 R230-R233 R237-R248 R252-R262 R269-R291 R294-R297 R300 R302 R307-R338 R344 R347-R350 R352 R358 R359 R363 R364 R367 R368 R371-R378 R380-R391 R394 R395 R398-R400 R406-R408 R410 R411 R437 R438 R444-R446 R448 R453 R455 R464 R468-R472 R476 R478 R484 R486 R495 R496 R500 R501 R506-R509 R511 R512 R515 R518-R520 R522-R524 R528-R530 R533 R535 R540-R542 R546 R548 R573-R576 R636 R658 R668 R684 R687 R697 R702 R704 R707 R725 R745 R747 R757 R759 R762-R764 R767 R776 R785 R792 R794 R839 R841-R843 R857-R867 R872-R875 R880 R881 R883-R898 R913-R915 R917 R923 R924 R928-R931 R939 R945 R946 R948 R949 R982 R984-R996 R999 R1001 R1019 R1029-R1052 R1054-R1066 R1073-R1075 R1119 R1121 R1125 R1126 R1129-R1131 R1134 R1138-R1141 R1151-R1154 R2295 R2298 R5283-R5285 R5287-R5304 R5311 R5316-R5320 R5322 R5330 R5333 R5338-R5341 R5379 R5380 R5387 R5388 R5390-R5394 R5398 R5400-R5403 R5407 R5409-R5412 R5416 R5418-R5421 R5425 R5427-R5430 R5434 R5437-R5439 R5443 R5445-R5448 R5452 R5454-R5456 R5458-R5461 R5463 R5467 R5468 R5470 R5472-R5476 R5478-R5480 R5484 R5881-R5883 R5970 R5977-R5981 R5994 R5995 R5997-R5999 R6005-R6007 R6009 R6013 R6015 R6016 R6019-R6023 R6027 R6028 R6034-R6036 R6040 R6043-R6046 R6049 R6050 R6053 R6054 R6057 R6058 R6061 R6062 R6065-R6067 R6070 R6071 R6074-R6090 = RESISTOR: Tolerance: TOL; User Part Number: PART#
R33 R35 R43 R44 R113-R115 R235 R236 R249 R250 R292 R293 R301 R303-R306 R401 R403 R405 R413 R414 R416 R418 R420 R421 R423 R426 R427 R429-R432 R439-R443 R447 R449-R452 R458 R459 R461 R462 R465-R467 R475 R505 R514 R537 R544 R555 R569 R640 R654 R662 R676 R680 R693 R701 R722 R732 R740 R746 R754 R766 R770 R779 R791 R922 R925-R927 R941 R942 R947 R968 R969 R976 R977 R981 R1006-R1010 R1014 = RESISTOR: Tolerance: TOL; User Part Number: PART#; signal model: RESISTOR_0402_0_0
R85 R98 R99 R263-R267 R299 R340 R341 R353 R412 R415 R417 R419 R422 R424 R425 R428 R433-R436 R483 R485 R845-R852 R970-R975 R1003 = R: Tolerance: TOL; User Part Number: PART#
R86 = RES 100K OHM 1.0% 1/16W 0402: Tolerance: TOL; User Part Number: PART#
R92 R94-R97 R178 R179 R487 R488 R490 R491 R558 R559 R643 R644 R666 R667 R855 R856 R940 R1025-R1028 R5286 = RES 0 OHM 5% 1/16W 0402 SMD: Tolerance: TOL; User Part Number: PART#
R93 R480-R482 R493 R494 R497 R498 R950 R951 = RES 0 OHM 5% 1/16W 0402 SMD: Tolerance: TOL; User Part Number: PART#; signal model: RES_0_OHM_5%_1/16W_0402_SMD_0402_DNI_DNI
R190 R229 R298 R980 R5996 R6037 R6038 = RESISTOR: Tolerance: *; User Part Number: *
R402 R404 R690 R718 R728 R736 R1024 R5312 R5323 = RESISTOR: User Part Number: PART#; Tolerance: TOL
R513 R534 = RES 10 OHM 1.0% 1/16W 0402: Tolerance: TOL; User Part Number: PART#
R521 R760 = RES: Tolerance: TOL; User Part Number: PART#
R539 = RES 10.0K OHMS 1.0% 1/16W 0402: Tolerance: TOL; User Part Number: PART#
R553 R5324 R5875 R5876 R6092 R6097-R6099 = Resistor, 0402: Tolerance: TOL; User Part Number: PART#
R670 = RES 0 OHM 5% 1/16W 0402 SMD: Tolerance: TOL; User Part Number: PART#; signal model: RESISTOR_0402_DNI_DNI
R681 R703 R750 R952 R997 R998 = RESISTOR
R953-R967 = RESISTOR: Tolerance: TOL; User Part Number: PART#; signal model: RESISTOR_0402_33_33
R1098 R1100 R1101 R1105 R1106 R1110 R1111 R5893 R5894 R5971-R5973 R6041 R6042 R6093-R6096 = Resistor, 0402_0: Tolerance: TOL; User Part Number: PART#
R5466 R5469 R5690 = RES0603_9: Tolerance: TOL; User Part Number: PART#
R5692 R5963 R5964 = RES0603_9: Tolerance: *; User Part Number: *
S1-S8 S10 S13-S18 = TS-A02SA-2-S100_0: User Part Number: *
ST1-ST6 ST8-ST11 ST13 ST16 ST18-ST21 = SHORT: User Part Number: *
SW1 SW4-SW6 = SPST4
SW2 SW3 = 76SB08
SW8 = SW SLIDE-DPDT: Tolerance: TOL; User Part Number: PART#
SW9 SW10 = SPST2
TP1-TP3 TP21 TP22 TP32 TP33 TP39-TP54 TP56 TP60 TP62-TP65 TP72 TP73 TP79 TP80 TP91 TP92 TP97 TP98 TP107-TP109 TP122 TP123 TP132-TP134 TP138 TP139 TP154 TP163-TP167 TP169 TP171-TP193 = VIA_0: User Part Number: *; Tolerance: *
U1 = FM6_2486A_V1_3.9_PCIe
U2 U10 U11 U13 U14 U16 U17 U40-U42 U79 = MAX3378_0: User Part Number: *; Tolerance: *
U3-U7 = MT40A1G16HBA-083E_1
U12 = 202718-1x1
U15 = 88E1111_3: Tolerance: *; User Part Number: *
U18 U19 = SN74AVC4T234ZSUR
U20 = DRTR5V0U2SR-7
U21 = CY7C68013A_0: User Part Number: *
U22 = MAX811_0: Tolerance: TOL; User Part Number: PART#
U23 U29 = 10M16SCU324
U24 U25 = IDTQS3861_0
U28 = MAX811_0: User Part Number: PART#; Tolerance: TOL
U31 = MAX6581_0: Tolerance: ?; User Part Number: 24TQFN-EP
U32 U33 = LTC2497
U34 = Si53311_2
U35 = Si52204
U36 U37 = Si5338A_1: User Part Number: *
U38 = LMK05028_2
U39 U80 = OSC_ALT_0
U43 U45 U81 = FXMA2102UMX
U44 = 24LC32A: User Part Number: *
U46 = DS1339C_0: User Part Number: part_number
U47 U50 = FDMC8010_0
U48 = LTC4218CDHC-12
U49 = LTM4623EV#PBF_5
U51 = LTC4365_DFN_0: User Part Number: *
U52 = LTM4623EV#PBF_6
U53 U58 = LTM4678EY#PBF_3
U54 = LTC3888IUHG-1#PBF_2
U57 = LTC3880-M0001_13: Tolerance: TOL; User Part Number: PN
U59 = LTC3880-M0001_15
U60-U64 U68 U70 U71 = LTM4608AEV#PBF_1: Tolerance: TOL
U65 U66 U72 = LTM4623EV#PBF_4
U67 U69 = NCP51200: Tolerance: TOL; User Part Number: K77668-001
U82 = LM339PW
U83 = FDMC8878_VER2: User Part Number: *
U84 = LTC4357: User Part Number: *
U87-U90 = LTC7051AV#PBF_2: Tolerance: TOL
V2-V4 V8-V13 V16-V25 = SENSE_PAD: User Part Number: *
X1 = OSC_ALT: User Part Number: *
X2 X3 = OSC_ALT_1
Y1 Y3-Y5 = CRYSTAL_SM_13: User Part Number: *
Y2 = OSC_Si570_0: Tolerance: ?; User Part Number: OSC_SMD_8PIN_3_2x5

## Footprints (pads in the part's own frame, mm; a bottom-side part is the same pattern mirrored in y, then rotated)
1X3_HDR_TH
  rect 1.524x1.524 hole 1.016: 1(0,0)
  round 1.524 hole 1.016: 2(2.54,0) 3(5.08,0)
2X8A_81_MXP-S50-0-4-GENERIC
  round 0.52 smd: 1(-14,-2) 2(-10,-2) 3(-6,-2) 4(-2,-2) 5(2,-2) 6(6,-2) 7(10,-2) 8(14,-2) 9(14,2) 10(10,2) 11(6,2) 12(2,2) 13(-2,2) 14(-6,2) 15(-10,2) 16(-14,2)
  round 1.651 hole 1.143: M1(0,0) M2(8,0)
